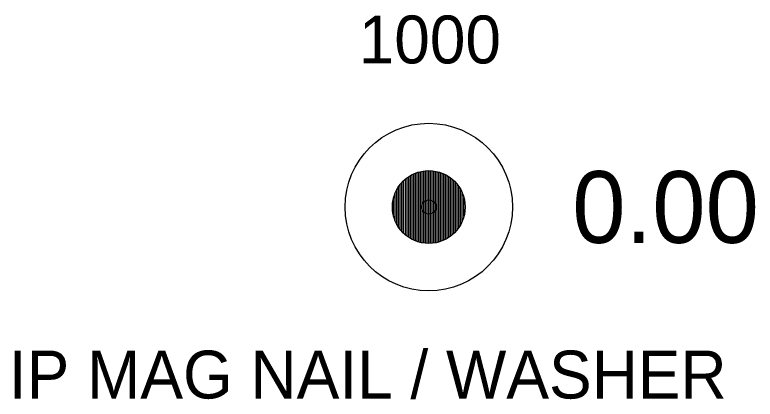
# Model space of a CAD drawing. Extents: x 1740701 to 1743138, y 748181 to 751839.
# Drawn here: x 1740700.81 to 1740716.29, y 748181.32 to 748189.35 of the extents above; entities that cross this region are included whole.
import ezdxf

# ---------------------------------------------------------------- set-up
doc = ezdxf.new("R2010")
doc.units = 0
for name, color, linetype in [('RD_EX_DV_Prop_txCode', 7, 'Continuous'), ('RD_EX_DV_PropPin', 7, 'Continuous'), ('RD_EX_TX_DV_Prop_ELEV', 7, 'Continuous'), ('RD_SMD_Locator', 7, 'Continuous')]:
    doc.layers.add(name, color=color, linetype=linetype)

msp = doc.modelspace()

# ---------------------------------------------------------------- linework, layer by layer
at = {"layer": 'RD_EX_DV_PropPin'}
for p, q in [((1740709.292, 748184.595), (1740709.292, 748186.076)), ((1740709.327, 748184.587), (1740709.327, 748186.083)), ((1740709.362, 748184.581), (1740709.362, 748186.089)), ((1740709.397, 748184.577), (1740709.397, 748186.093)), ((1740709.432, 748184.575), (1740709.432, 748186.095)), ((1740709.467, 748184.574), (1740709.467, 748186.096)), ((1740709.502, 748184.575), (1740709.502, 748186.095)), ((1740709.537, 748184.577), (1740709.537, 748186.093)), ((1740709.572, 748184.581), (1740709.572, 748186.089)), ((1740709.607, 748184.587), (1740709.607, 748186.083)), ((1740709.642, 748184.595), (1740709.642, 748186.076)), ((1740709.012, 748184.725), (1740709.012, 748185.945)), ((1740709.047, 748184.701), (1740709.047, 748185.97)), ((1740709.082, 748184.679), (1740709.082, 748185.992)), ((1740709.117, 748184.66), (1740709.117, 748186.011)), ((1740709.152, 748184.642), (1740709.152, 748186.028)), ((1740709.187, 748184.628), (1740709.187, 748186.043)), ((1740709.222, 748184.615), (1740709.222, 748186.056)), ((1740709.257, 748184.604), (1740709.257, 748186.067)), ((1740709.677, 748184.604), (1740709.677, 748186.067)), ((1740709.712, 748184.615), (1740709.712, 748186.056)), ((1740709.747, 748184.628), (1740709.747, 748186.043)), ((1740709.782, 748184.642), (1740709.782, 748186.028)), ((1740709.817, 748184.66), (1740709.817, 748186.011)), ((1740709.852, 748184.679), (1740709.852, 748185.992)), ((1740709.887, 748184.701), (1740709.887, 748185.97)), ((1740709.922, 748184.725), (1740709.922, 748185.945)), ((1740708.872, 748184.861), (1740708.872, 748185.809)), ((1740708.907, 748184.82), (1740708.907, 748185.85)), ((1740708.942, 748184.784), (1740708.942, 748185.886)), ((1740708.977, 748184.753), (1740708.977, 748185.917)), ((1740709.957, 748184.753), (1740709.957, 748185.917)), ((1740709.992, 748184.784), (1740709.992, 748185.886)), ((1740710.027, 748184.82), (1740710.027, 748185.85)), ((1740710.062, 748184.861), (1740710.062, 748185.809)), ((1740708.767, 748185.037), (1740708.767, 748185.633)), ((1740708.802, 748184.966), (1740708.802, 748185.705)), ((1740708.837, 748184.909), (1740708.837, 748185.762)), ((1740710.097, 748184.909), (1740710.097, 748185.762)), ((1740710.132, 748184.966), (1740710.132, 748185.705)), ((1740710.167, 748185.037), (1740710.167, 748185.633)), ((1740708.732, 748185.139), (1740708.732, 748185.531)), ((1740710.202, 748185.139), (1740710.202, 748185.531))]:
    msp.add_line(p, q, dxfattribs=at)
for radius in [1.75, 0.761]:
    msp.add_circle((1740709.467, 748185.335), radius, dxfattribs=at)
at = {"layer": 'RD_SMD_Locator'}
msp.add_circle((1740709.467, 748185.335), 0.15, dxfattribs=at)

# ---------------------------------------------------------------- texts
at = {"layer": 'RD_EX_DV_Prop_txCode'}
for s, p in [('1000', (1740708.002, 748188.335)), ('IP MAG NAIL / WASHER', (1740700.687, 748181.335))]:
    msp.add_text(s, height=1, dxfattribs=at).set_placement(p)
at = {"layer": 'RD_EX_TX_DV_Prop_ELEV'}
msp.add_text('0.00', height=1.5, dxfattribs=at).set_placement((1740712.467, 748184.585))

doc.saveas('drawing.dxf')
